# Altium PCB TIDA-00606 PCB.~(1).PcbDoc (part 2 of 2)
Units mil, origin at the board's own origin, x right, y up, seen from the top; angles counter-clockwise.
Board outline 3100 x 2950 mil, 4 copper layers (Top Layer, InternalPlane1, MidLayer1, Bottom Layer); 112 components, 59 nets, 260 pads, 440 vias.
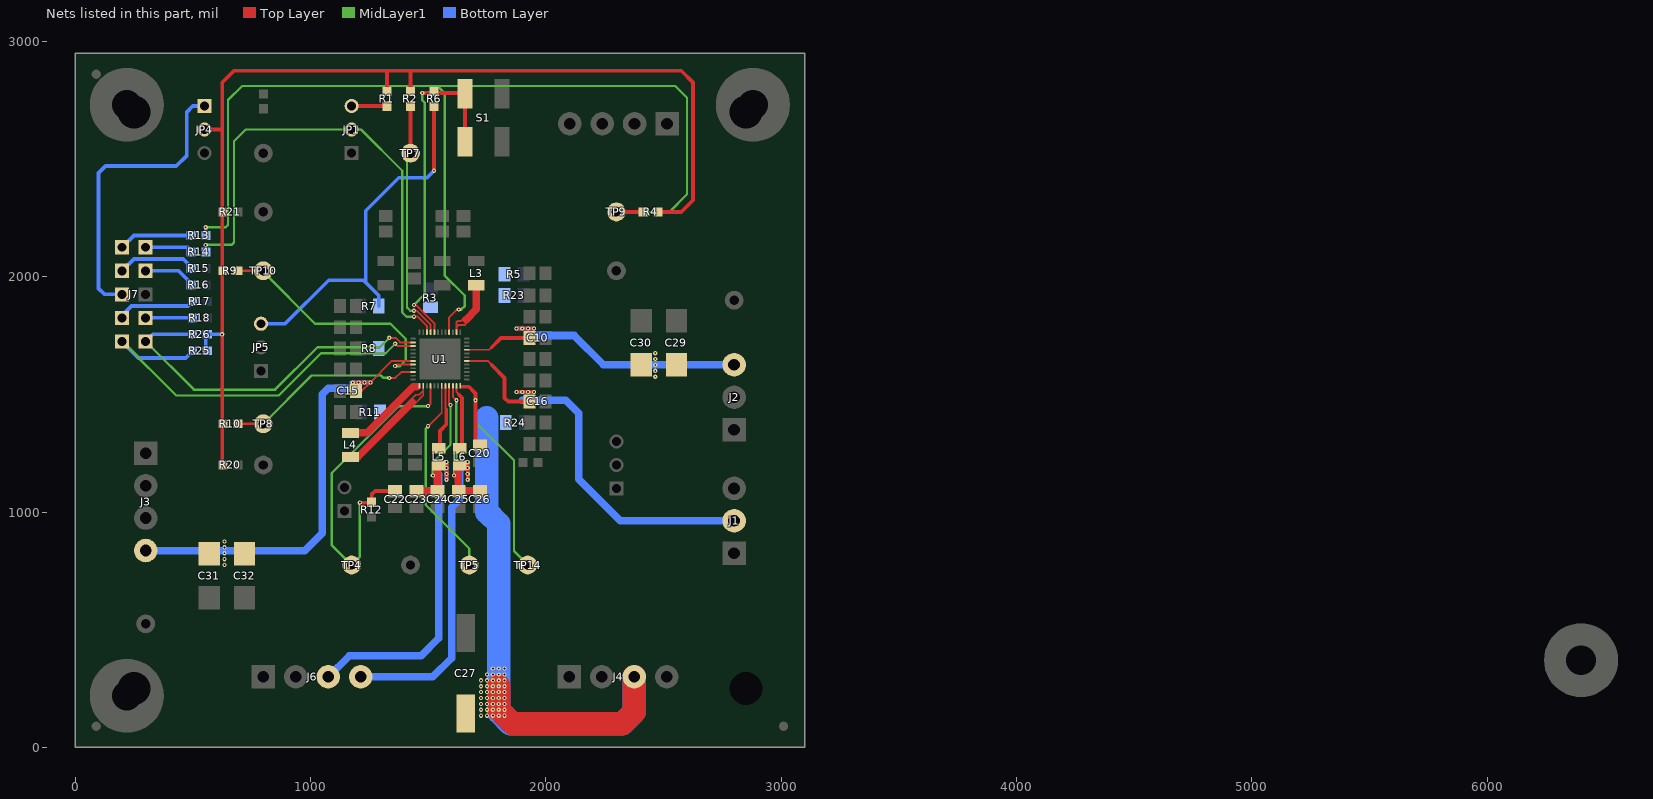
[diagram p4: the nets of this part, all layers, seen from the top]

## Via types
v1: diameter 18, hole 8, Top Layer to Bottom Layer, tented both sides, 440 vias

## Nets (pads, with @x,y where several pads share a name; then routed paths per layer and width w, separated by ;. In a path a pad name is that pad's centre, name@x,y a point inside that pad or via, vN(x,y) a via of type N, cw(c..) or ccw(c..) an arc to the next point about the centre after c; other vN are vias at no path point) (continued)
L3: L3.1 U1.38 | length 314.1
  Top Layer w8: U1.38@1620.87,1768.11 1620.87,1785.3 ; 1653.93,1827.07 1637.87,1811 1625,1811 1620.87,1806.87 1620.87,1785.3 ; 1677,1816 1656,1795 1630.57,1795 1620.87,1785.3
  Top Layer w32: 1661,1817 1705,1861 L3.1@1705,1963.82
L4A: L4.2 U1.13 | length 362.1
  Top Layer w32: L4.2@1170,1336.18 1241.18,1336.18 1437,1532 1451,1532
L4B: L4.1 U1.14 | length 526.6
  Top Layer w8: 1421,1472 1447.41,1498.41 1462.84,1498.41 1479.13,1514.7 ; 1440.07,1456.93 1479.13,1496 1479.13,1514.7 ; U1.14@1479.13,1531.89 1479.13,1514.7
  Top Layer w32: L4.1@1170,1233.82 1199.98,1233.82 1433.08,1466.92
LS1: C16.1 J1.2 U1.30 | length 1799.1
  Top Layer w8: U1.30@1668.11,1642.13 1752.87,1642.13 1770,1625
  Top Layer w16: 1770,1625 1825,1570 1825,1485 1840,1470 C16.1@1920,1470 ; v1(1875,1510) v1(1900,1510) v1(1925,1510) v1(1950,1510)
  Bottom Layer w16: v1(1875,1510) v1(1900,1510) v1(1925,1510) v1(1950,1510)
  Bottom Layer w32: 1900,1475 2085,1475 2140,1420 2140,1140 2317,963 J1.2@2800,963
LS2: C10.1 C29.1 C30.1 J2.3 U1.33 | length 1350.6
  Top Layer w8: U1.33@1668.11,1689.37 1759.37,1689.37 1770,1700
  Top Layer w16: 1770,1700 1810,1740 C10.1@1920,1740 ; v1(1875,1780) v1(1900,1780) v1(1925,1780) v1(1950,1780)
  Bottom Layer w16: v1(1875,1780) v1(1900,1780) v1(1925,1780) v1(1950,1780)
  Bottom Layer w32: 1925,1750 2120,1750 2245,1625 v1(2465,1625) 2800,1625 J2.3@2800,1625.59 J2.3@2800,1626
  other v1: 2465,1575 2465,1600 2465,1650 2465,1675
LS3: C15.2 C31.1 C32.1 J3.4 U1.7 | length 1930.6
  Top Layer w8: C15.2@1215,1515 1218.56,1515 1253.56,1550 1345.68,1642.13 U1.7@1431.89,1642.13
  Top Layer w16: v1(1180,1550) v1(1205,1550) v1(1230,1550) 1253.56,1550 v1(1255,1550)
  Bottom Layer w16: v1@1175,1550 v1(1180,1550) v1(1205,1550) v1(1230,1550) v1(1255,1550)
  Bottom Layer w32: J3.4@300,836 976,836 1050,910 1050,1500 1075,1525 1175,1525
  other v1: 635,775 635,800 635,825 635,850 635,875
NetC20_2: C20.2 TP14.1 U1.24 | length 1074.4
  Top Layer w16: 1641,1532 1673,1532 1701,1504 v1(1701,1475) C20.2@1701,1294
  MidLayer1 w10: v1(1701,1475) 1701,1384 1865,1220 1865,835 TP14.1@1925,775
NetJ7_1: J7.1 R13.1 | length 320.7
  Bottom Layer w16: J7.1@200,2125 250,2175 R13.1@493.5,2175 R13.1@500,2175
NetJ7_2: J7.2 R14.1 | length 208.3
  Bottom Layer w16: J7.2@300,2125 480,2125 R14.1@500,2105
NetJ7_3: J7.3 R15.1 | length 337.3
  Bottom Layer w16: J7.3@200,2025 250,2075 460,2075 R15.1@500,2035
NetJ7_4: J7.4 R16.1 | length 224.9
  Bottom Layer w16: J7.4@300,2025 440,2025 R16.1@500,1965
NetJ7_5: J7.5 JP4.1 | length 1276.8
  Bottom Layer w16: J7.5@200,1925 125,1925 100,1950 100,2440 130,2470 430,2470 475,2515 475,2700 500,2725 JP4.1@550,2725
NetJ7_7: J7.7 R17.1 | length 334.9
  Bottom Layer w16: J7.7@200,1825 200,1835 240,1875 480,1875 R17.1@500,1895
NetJ7_8: J7.8 R18.1 | length 200
  Bottom Layer w16: J7.8@300,1825 R18.1@498.5,1825 R18.1@500,1825
NetJP1_3: JP1.3 R1.1 | length 150
  Top Layer w16: JP1.3@1175,2725 R1.1@1325,2725
NetL5_2: L5.2 U1.20 | length 269.4
  Top Layer w8: U1.20@1573.62,1531.89 1573.62,1438.85 1576.87,1435.6
  Top Layer w16: L5.2@1538,1280 1550,1292 1550,1345 1577,1372 1577,1435.47 1576.87,1435.6
NetL6_2: L6.2 U1.23 | length 281.7
  Top Layer w8: U1.23@1620.87,1531.89 1620.87,1509.13 1630,1500
  Top Layer w16: L6.2@1625,1280 1627.59,1281.03 L6.2@1630,1282 ; L6.2@1628,1280 L6.2@1630,1282 ; 1630,1500 1644,1486 1644,1282 L6.2@1630,1282
NINT: R2.1 TP7.1 U1.45 | length 1021.1
  Top Layer w8: v1(1440,1855) 1451.86,1855 1510.63,1796.23 U1.45@1510.63,1768.11
  Top Layer w16: TP7.1@1425,2525 R2.1@1425,2723.5 R2.1@1425,2725
  MidLayer1 w10: TP7.1@1425,2525 1410,2510 1410,1869 1424,1855 v1(1440,1855)
NPFO: R10.2 TP8.1 U1.10 | length 851.3
  Top Layer w8: v1(1335,1570) 1361.21,1570 1386.09,1594.88 U1.10@1431.89,1594.88
  Top Layer w12: R10.2@680,1375 R10.2@691.5,1375 TP8.1@800,1375
  MidLayer1 w10: TP8.1@800,1375 1005,1580 1300,1580 1310,1570 v1(1335,1570)
NWAKEUP: R4.1 R13.2 TP9.1 U1.40 | length 4658
  Top Layer w8: U1.40@1589.37,1768.11 1589.37,1827.58 1621.79,1860 v1(1630,1860)
  Top Layer w16: TP9.1@2300,2275 R4.1@2413.5,2275 R4.1@2425,2275
  MidLayer1 w10: v1(555,2210) 640,2210 650,2220 650,2750 710,2810 1540,2810 ; v1@1630,1856 v1(1630,1860) 1640,1860 1656,1876 1656,1919 1570,2005 1570,2780 1540,2810 ; TP9.1@2300,2275 2525,2275 2600,2350 2600,2760 2550,2810 1540,2810
  Bottom Layer w16: R13.2@555,2175 v1(555,2210)
PB: R6.1 S1.2 S1.3 U1.44 | length 1462.2
  Top Layer w8: v1(1440,1880) 1448.07,1880 1526.38,1801.69 U1.44@1526.38,1768.11
  Top Layer w16: v1(1475,2780) 1653.5,2780 1656.1,2777.4 S1.3@1656.1,2572.6
  MidLayer1 w10: v1(1440,1880) 1485,1925 1485,2740 1475,2750 v1(1475,2780)
PFI: C22.2 R12.2 TP4.1 U1.16 | length 1490.3
  Top Layer w8: v1(1500,1450) 1510.63,1460.63 U1.16@1510.63,1531.89
  Top Layer w16: v1(1210,1040) 1260,1040 R12.2@1260,1041.5 1260,1075 1275,1090 C22.2@1340,1090
  MidLayer1 w10: v1(1210,1040) 1210,810 TP4.1@1175,775 1090,860 1090,1165 1375,1450 v1(1500,1450)
PGOOD: R9.2 TP10.1 U1.8 | length 1062.9
  Top Layer w8: v1(1360,1620) 1366.38,1626.38 U1.8@1431.89,1626.38
  Top Layer w10: R9.2@680,2025 R9.2@691.5,2025 TP10.1@800,2025
  MidLayer1 w10: TP10.1@800,2020 1020,1800 1340,1800 1405,1735 1405,1645 1380,1620 v1(1360,1620)
PGOOD_BU: TP5.1 U1.19 | length 861.6
  Top Layer w8: v1(1500,1365) 1557.87,1422.87 U1.19@1557.87,1531.89
  MidLayer1 w10: v1(1500,1365) 1490,1355 1490,1030 1675,845 TP5.1@1675,775
PWR_EN: JP1.2 R14.2 U1.46 | length 2145.6
  Top Layer w8: v1(1440,1830) 1455.64,1830 1494.88,1790.76 U1.46@1494.88,1768.11
  MidLayer1 w10: v1(555,2135) 665,2135 675,2145 675,2575 725,2625 JP1.2@1175,2625 1215,2625 1390,2450 1390,1848 1408,1830 v1(1440,1830)
  Bottom Layer w16: R14.2@555,2105 v1(555,2135)
SCL: J7.9 R25.1 U1.3 | length 1768.8
  Top Layer w8: v1(1360,1715) 1369.88,1705.12 U1.3@1431.89,1705.12
  MidLayer1 w10: J7.9@200,1720 J7.9@200,1725 430,1495 865,1495 1045,1675 1320,1675 v1(1360,1715)
  Bottom Layer w16: J7.9@200,1725 270,1655 470,1655 R25.1@500,1685
SDA: J7.10 R26.1 U1.2 | length 1528.3
  Top Layer w8: v1(1335,1740) 1361.87,1740 1381,1720.87 U1.2@1431.89,1720.87
  MidLayer1 w10: J7.10@300,1725 505,1520 850,1520 1030,1700 1295,1700 v1(1335,1740)
  Bottom Layer w16: J7.10@300,1725 330,1755 R26.1@498.5,1755 R26.1@500,1755
VDCDC5: C23.2 C24.2 J6.3 L5.1 U1.21 | length 1987.6
  Top Layer w8: U1.21@1589.37,1531.89 1589.37,1460.63 v1(1595,1455) v1@1595,1450
  Top Layer w16: v1(1578,1137) v1(1578,1162) v1(1578,1187) v1(1578,1212)
  Top Layer w32: C23.2@1448,1090 1538,1090 L5.1@1538,1190
  MidLayer1 w10: v1(1520,1155) 1520,1211 1595,1286 v1(1595,1455)
  Bottom Layer w16: v1(1578,1137) v1(1578,1162) v1(1578,1187) v1(1578,1212)
  Bottom Layer w32: J6.3@1076,300 1166,390 1470,390 1545,465 1545,1160
VDCDC6: C25.2 C26.2 J6.4 L6.1 U1.22 | length 1959.8
  Top Layer w8: U1.22@1605.12,1531.89 1605.12,1489.88 v1(1620,1475)
  Top Layer w16: v1(1668,1137) v1(1668,1162) v1(1668,1187) v1(1668,1212)
  Top Layer w32: L6.1@1628,1190 1628,1090 C26.2@1718,1090
  MidLayer1 w10: v1(1610,1155) 1610,1211 1620,1221 v1(1620,1475)
  Bottom Layer w16: v1(1668,1137) v1(1668,1162) v1(1668,1187) v1(1668,1212)
  Bottom Layer w32: J6.4@1210,300 J6.4@1213.39,300 1520,300 1600,380 1600,1020 1635,1055 1635,1175
VIO: JP4.2 R1.2 R2.2 R4.2 R9.1 R10.1 R20.1 R21.2 R25.2 R26.2 | length 4737.1
  Top Layer w16: JP4.2@550,2625 625,2625 ; R20.1@625,1200 v1(625,1755) 625,2275 625,2625 ; R1.2@1325,2780 R1.2@1325,2786.5 1325,2875 ; R2.2@1425,2780 R2.2@1425,2786.5 1425,2875 ; R4.2@2480,2275 2575,2275 2625,2325 2625,2825 2575,2875 1425,2875 ; 625,2625 625,2825 675,2875 1325,2875 ; 1325,2875 1425,2875
  Bottom Layer w16: R25.2@555,1685 555,1755 R26.2@561.5,1755 v1(625,1755)
VSYS: C27.1 J4.3 JP5.3 R3.2 R5.2 R6.2 R7.1 R8.1 R11.1 R23.2 R24.2 | length 4499.9
  Top Layer w16: v1(1525,2450) R6.2@1525,2723.5 R6.2@1525,2725
  Top Layer w100: v1(1800,260) v1(1800,235) v1(1800,210) v1(1800,185) v1(1800,160) v1(1825,135) 1860,100 2325,100 2376,151 J4.3@2376,300
  Bottom Layer w16: JP5.3@790,1800 892.47,1800 1077.47,1985 1225,1985 1235,1975 ; R7.1@1290,1875 1290,1920 1235,1975 ; v1(1525,2450) 1495,2420 1375,2420 1235,2280 1235,1975
  Bottom Layer w40: J4.3@2375,301 J4.3@2376,300
  Bottom Layer w100: 1750,1400 1750,1000 1800,950 v1(1800,335) v1(1800,310) v1(1800,285) v1(1800,260) v1(1800,235) v1(1800,210) v1(1800,185) v1(1800,160) 1800,150 1850,100 2325,100 2376,151 2376,300 J4.3@2376,301
  other v1: 1725,135 1750,135 1775,135 1800,135 1725,160 1750,160 1775,160 1825,160 1725,185 1750,185 1775,185 1825,185 1725,210 1750,210 1775,210 1825,210 1725,235 1750,235 1775,235 1825,235 1725,260 1750,260 1775,260 1825,260 1725,285 1750,285 1775,285 1825,285 1750,310 1775,310 1825,310 1775,335 1825,335
pads on no net: FID1.1 FID2.1 FID3.1 H1.1 H2.1 H3.1 H4.1 H5.0 H6.0 H7.0 H8.0 H9.0 H10.0 H11.0 H12.0 U1.28 U1.29

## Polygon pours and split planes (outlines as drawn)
GND on MidLayer1 "Mid Layer-GND" (solid, remove dead copper, pour order 8): 0,0 3100,0 3100,2950 0,2950
GND on Top Layer "Top Layer-GND" (solid, remove dead copper, pour order 5): 0,0 3100,0 3100,2950 0,2950
VSYS on Bottom Layer "Bottom Layer-VSYS" (solid, remove dead copper, pour order 3): 1837,1275 1260,1275 1260,2100 1837,2100
GND on Bottom Layer "Bottom Layer-GND" (solid, remove dead copper, pour order 7): 0,0 3100,0 3100,2950 0,2950
GND on InternalPlane1 (split plane): 3079.9,20.1 20.1,20.1 20.1,2929.9 3079.9,2929.9

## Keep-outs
Keep-Out Layer:
  lines w10: 3100,-5 0,-5 ; 3105,0 3105,2950 ; -5,0 ccw(c0,0) 0,-5 ; -5,0 ccw(c0,0) 0,-5 ; -5,0 ccw(c0,0) 0,-5 ; -5,0 ccw(c0,0) 0,-5 ; -5,0 ccw(c0,0) 0,-5 ; -5,0 ccw(c0,0) 0,-5 ; -5,0 -5,2950 ; -5,2950 cw(c0,2950) 0,2955 ; -5,2950 cw(c0,2950) 0,2955 ; -5,2950 cw(c0,2950) 0,2955 ; -5,2950 cw(c0,2950) 0,2955 ; -5,2950 cw(c0,2950) 0,2955 ; -5,2950 cw(c0,2950) 0,2955 ; 0,2955 3100,2955 ; 3100,2955 cw(c3100,2950) 3105,2950 ; 3100,2955 cw(c3100,2950) 3105,2950 ; 3100,2955 cw(c3100,2950) 3105,2950 ; 3100,2955 cw(c3100,2950) 3105,2950 ; 3100,2955 cw(c3100,2950) 3105,2950 ; 3100,2955 cw(c3100,2950) 3105,2950
  text ".Layer_Name" at 577,-858.49 h60

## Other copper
Top Layer:
  pour cut-out: 1505,1250 1660,1250 1660,1220 1505,1220
  pour cut-out: 1115,1310 1225,1310 1225,1255 1115,1255
  pour cut-out: 1650,2040 1760,2040 1760,1985 1650,1985
  pour cut-out: 1505,2040 1615,2040 1615,1985 1505,1985
  pour cut-out: 1265,2045 1375,2045 1375,1990 1265,1990
  region net IN_DC2: 1400,1915 1480,1915 1455,1890
  region net IN_DC2: 1400,2015 1479.37,2015 1480,1915 1400,1915
  region net IN_DC2: 1521,1823 1538,1806 1546,1806 1546,1835
  region net L3: 1625,1811 1620.87,1806.87 1620.87,1788 1623.57,1788 1630.57,1795 1656,1795 1677,1816 1661,1832 1661,1833 1659.87,1833 1637.87,1811
  region net L4B: 1421,1472 1438,1455 1479,1496 1479.13,1496 1479.13,1514.7 1462.84,1498.41 1447.41,1498.41
  region net L2: 1554,1868 1586,1868 1586,1861 1554,1829
  region net CC: 2036,1160 2036,1225 1945,1225 1945,1160
  region net 1V1_VCC_GXB: 1600,2218 1535,2218 1535,2127 1600,2127
  region net 2V5: 1690,2218 1625,2218 1625,2127 1690,2127
  region net IN_DC3: 1874.5,2055 1874.5,1990 1965.5,1990 1965.5,2055
  region net IN_DC4: 1177,1465 1177,1400 1268,1400 1268,1465
  region net IN_DC1: 1177,1915 1177,1850 1268,1850 1268,1915
  region net IN_LDO: 1177,1735 1177,1670 1268,1670 1268,1735
  region net LS3: 1177,1555 1177,1490 1268,1490 1268,1555
  region net IN_LS3: 1177,1645 1177,1580 1268,1580 1268,1645
  region net 1V8: 1177,1825 1177,1760 1268,1760 1268,1825
  region net LS1: 1867,1510 1867,1445 1958,1445 1958,1510
  region net IN_LS1: 1867,1600 1867,1535 1958,1535 1958,1600
  region net IN_LS2: 1867,1690 1867,1625 1958,1625 1958,1690
  region net LS2: 1867,1780 1867,1715 1958,1715 1958,1780
  region net IN_BIAS: 1874,1960 1874,1895 1965,1895 1965,1960
  region net LS3: 740,885 525,885 525,765 740,765
  region net LS2: 2360,1565 2575,1565 2575,1685 2360,1685
  region net VDCDC5: 1578,1220 1513,1220 1513,1129 1578,1129
  region net VDCDC6: 1668,1220 1603,1220 1603,1129 1668,1129
  region net INT_LDO: 1867,1870 1867,1805 1958,1805 1958,1870
  region net VSYS: 1620,50 1850,50 1850,350 1750,350 1620,220
  region net IN_BU: 1867,1420 1867,1355 1958,1355 1958,1420
  region net 1V1_VCC: 1365,2225 1275,2225 1275,2130 1365,2130
  region net L1: 1285,1945 1285,1890 1315,1860 1355,1860 1355,1945
  region net IN_DC1: 1395,1755 1380,1740 1385,1735 1415,1735 1415,1740
  region net IN_LDO: 1245,1730 1265,1730 1321,1674 1330,1670 1245,1670
  region net 1V8: 1260,1820 1285,1820 1310,1795 1310,1725 1300,1725 1260,1765
  region net IN_DC4: 1268,1465 1328,1525 1365,1525 1365,1497 1268,1400
  region net LS3: 1268,1490 1318.56,1540.56 1318.56,1613.56 1255,1550
  region net IN_LS3: 1268,1580 1335,1647 1335,1660 1240,1660 1230,1650 1230,1580
  region net IN_DC3: 1870,2052.5 1870,1987.5 1961,1987.5 1961,2052.5
  region net L2: 1600,1985 1600,1875 1560,1835 1555,1835 1554,1848.5 1525,1875 1525,1985
  region net L3: 1670,1985 1740,1985 1740,1875 1710,1845 1670,1845
  region net 3V3: 1494.88,1490.54 1391,1386.66 1391,1368 1333,1310 1333,1242 1473,1242 1473,1450 1494.88,1471.88
  region net NetL5_2: 1516.46,1250 1516.46,1326.46 1570,1380 1585,1375 1585,1250
  region net NetL6_2: 1665,1250 1605,1250 1605,1415 1640,1440 1650,1440 1665,1415
  text ".Layer_Name" at 577,-858.49 h60
Bottom Layer:
  region net 2V5: 1625,2218 1690,2218 1690,2127 1660,2127 1625,2162
  region net GND: 1460,1740 1640,1740 1640,1560 1460,1560
  region net IN_BIAS: 1965,1892.5 1965,1965 1875,1965 1874,1892.5
  region net CC: 1945,1225 1945,1160 2036,1160 2036,1225
  region net IN_DC4: 1165,1465 1165,1400 1250,1400 1250,1465
  region net IN_LDO: 1165,1735 1165,1665 1250,1665 1251,1737.5
  region net IN_DC1: 1159.5,1915 1159.5,1850 1250.5,1850 1250.5,1915
  region net IN_DC3: 1965.5,1990 1965.5,2055 1874.5,2055 1874.5,1990
  region net IN_DC2: 1400,1915 1550,1915 1550,1985 1400,1985
  region net 1V8: 1260.5,1760 1260.5,1825 1169.5,1825 1169.5,1760
  region net LS3: 1260.5,1490 1260.5,1555 1169.5,1555 1169.5,1490
  region net IN_LS3: 1265.5,1580 1265.5,1645 1174.5,1645 1174.5,1580
  region net LS1: 1958,1445 1958,1510 1867,1510 1867,1445
  region net IN_LS1: 1958,1535 1958,1600 1867,1600 1867,1535
  region net IN_LS2: 1958,1625 1958,1690 1867,1690 1867,1625
  region net LS2: 1958,1715 1958,1780 1867,1780 1867,1715
  region net LS3: 740,885 525,885 525,765 740,765
  region net LS2: 2360,1565 2575,1565 2575,1685 2360,1685
  region net VDCDC5: 1513,1129 1578,1129 1578,1220 1548,1220 1513,1185
  region net VDCDC6: 1602,1129 1667,1129 1667,1220 1637,1220 1602,1185
  region net 1V1_VCC: 1285,2225 1355,2225 1355,2127 1325,2127 1285,2160
  region net 1V1_VCC_GXB: 1535,2218 1600,2218 1600,2127 1570,2127 1535,2162
  region net 2V5: 1625,2218 1690,2218 1690,2127 1660,2127 1625,2162
  region net INT_LDO: 1958,1805 1958,1870 1867,1870 1867,1805
  region net VSYS: 1620,50 1850,50 1850,390 1750,390 1620,260
  region net IN_BU: 1958,1355 1958,1420 1867,1420 1867,1355
  region net IN_DC3: 1961,1987.5 1961,2052.5 1870,2052.5 1870,1987.5
  text ".Layer_Name" at 577,-858.49 h60

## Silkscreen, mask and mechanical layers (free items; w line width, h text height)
Top Overlay:
  region: 3050,2305 2750,2305 2750,2205 3050,2205
  lines w10: 1025,900 1025,2370 2110,2370 2110,900 1025,900
  text "DC1" at 2130,2880 h40 r180
  text "DC2" at 2290,2880 h40 r180
  text "DC3" at 2430,2880 h40 r180
  text "GND" at 2570,2880 h40 r180
  text "V3p3" at 370,2710 h30
  text "VIO" at 1005,2710 h30
  text "DC4" at 400,2510 h30
  text "GND" at 1005,2510 h30
  text "TIDA-00478" at 2445,2105 h50
  text "A" at 3010,2105 h50
  text "-" at 2945,2100 h50
  text "TPS65218" at 2665,2025 h50
  text "VSYS" at 610,1780 h30
  text "AC_D" at 610,1680 h30
  text "LS2" at 3030,1670 h40 r90
  text "GND" at 615,1580 h30
  text "+" at 2320,1560 h40 r90
  text "GND" at 70,1390 h40 r270
  text "IN_LS2" at 3030,1390 h40 r90
  text "DC3" at 2370,1290 h30
  text "LD01" at 70,1230 h40 r270
  text "GND" at 3030,1230 h40 r90
  text "EXT" at 2370,1080 h30
  text "EXT" at 3030,1070 h40 r90
  text "IN_LS3" at 70,1050 h40 r270
  text "GND" at 1070,960 h30 r90
  text "LS1" at 3030,910 h40 r90
  text "+" at 845,865 h40 r90
  text "LS3" at 70,790 h40 r270
  text "GND" at 3030,750 h40 r90
  text "GND" at 710,70 h40
  text "DC4" at 870,70 h40
  text "DC5" at 1030,70 h40
  text "DC6" at 1190,70 h40
  text "GND" at 2030,70 h40
  text "GND" at 2170,70 h40
  text "VSYS" at 2310,70 h40
  text "CC" at 2510,70 h40
  text ".Layer_Name" at 577,-858.49 h60
Bottom Overlay:
  text ".Layer_Name" at 577,-858.49 h60
Top Paste:
  text ".Layer_Name" at 577,-858.49 h60
Bottom Paste:
  text ".Layer_Name" at 577,-858.49 h60
Top Solder:
  text ".Layer_Name" at 577,-858.49 h60
  text ".Layer_Name" at 577,-858.49 h60
Bottom Solder:
  text ".Layer_Name" at 577,-858.49 h60
Drill Guide:
  text ".Layer_Name" at 577,-858.49 h60
M1 Board Outline:
  the board outline again, w10
  text ".Layer_Name" at 577,-858.49 h60
M2 Board Dimensions:
  rectangle: 0,-285.5 125,-160.5
  rectangle: 125,-410.5 500,-285.5
  lines w7: 0,-285.5 1000,-285.5 ; 125,-410.5 125,-160.5 ; 250,-410.5 250,-160.5 ; 500,-410.5 500,-160.5 ; 750,-410.5 750,-160.5 ; 0,-410.5 1000,-410.5 1000,-160.5 0,-160.5 0,-410.5
  text ".Layer_Name" at 577,-858.49 h60
M3 3D STEP Top:
  text ".Layer_Name" at 577,-858.49 h60
M4 3D STEP Bottom:
  text ".Layer_Name" at 577,-858.49 h60
M5 Assembly Top:
  lines w10: -292,-930.17 6308,-930.17 ; -292,-726.83 6310,-726.83 ; -292,-523.5 -292,-1133.5 3713,-1133.5 6310,-1133.5 6310,-523.5 -291.5,-523.5 -291.5,-1133.5 1284,-1133.5 ; 2173,-1133.5 2173,-523.5 ; 3440,-726.83 3440,-523.5 ; 4280,-726.83 4280,-523.5 ; 4902,-1140 4902,-937.17
  text "COMPONENTS MARKED 'DNP' SHOULD NOT BE POPULATED." at 1153.5,-318.5 h60
  text "ASSEMBLY VARIANT:" at 1153,-434 h60
  text ".VariantName" at 2189,-434 h60
  text "PCB VIEWED FROM TOP SIDE" at -228.5,-655.67 h60
  text "BOARD #:" at 2248,-655.67 h60
  text ".PRJ_Number" at 2793.5,-655.67 h60
  text "REV:" at 3638,-655.67 h60
  text ".PCB_Rev" at 3929.5,-655.67 h60
  text "SVN REV:" at 4476,-655.67 h60
  text ".VersionControl_RevNumber" at 4982,-655.67 h60
  text "IGNORE ->" at -228.5,-858.49 h60
  text "PLOT NAME =" at -228.5,-1064.34 h60
  text ".plot_File_Name" at 577,-1064.34 h60
  text "GENERATED    :" at 2250,-1064.34 h60
  text ".Print_Date" at 3119.5,-1064.34 h60
  text ".Print_Time" at 3848.5,-1064.34 h60
  text "TEXAS INSTRUMENTS" at 5113,-1064.34 h60
M6 Assembly Bottom:
  lines w10: -292.5,-727.33 6309.5,-727.33 ; -290.5,-930.67 6309.5,-930.67 ; 1115.5,-1140.5 1115.5,-937.67 ; 1737.5,-727.33 1737.5,-524 ; 2577.5,-727.33 2577.5,-524 ; 3844.5,-1134 3844.5,-524 ; 4733.5,-1134 6309,-1134 6309,-524 -292.5,-524 -292.5,-1134 2304.5,-1134 6309.5,-1134 6309.5,-524
  text "COMPONENTS MARKED 'DNP' SHOULD NOT BE POPULATED." at 6102,-318 h60
  text ".VariantName" at 5058,-434 h60
  text "ASSEMBLY VARIANT:" at 6097,-434 h60
  text ".VersionControl_RevNumber" at 1035.5,-656.17 h60
  text "SVN REV:" at 1541.5,-656.17 h60
  text ".PCB_Rev" at 2088,-656.17 h60
  text "REV:" at 2379.5,-656.17 h60
  text ".PRJ_Number" at 3224,-656.17 h60
  text "BOARD #:" at 3769.5,-656.17 h60
  text "PCB VIEWED FROM BOTTOM SIDE" at 6246,-656.17 h60
  text "IGNORE ->" at 2547.85,-858.49 h60
  text "TEXAS INSTRUMENTS" at 904.5,-1064.84 h60
  text ".Print_Time" at 2169,-1064.84 h60
  text ".Print_Date" at 2898,-1064.84 h60
  text "GENERATED    :" at 3767.5,-1064.84 h60
  text ".plot_File_Name" at 5440.5,-1064.84 h60
  text "PLOT NAME =" at 6246,-1064.84 h60
M9 Title Sheet:
  drawing of 57 lines, arcs and shapes, not listed
  text "1" at 739.84,8036.5 h70
  text "2" at 3235.5,8036.5 h70
  text "3" at 5724.84,8036.5 h70
  text "4" at 8231.51,8036.5 h70
  text "5" at 10730.5,8036.5 h70
  text "6" at 13235.5,8036.5 h70
  text "A" at -416.5,6893.5 h70
  text "A" at 14383.5,6893.5 h70
  text "B" at -416.5,4513.5 h70
  text "B" at 14383.5,4513.5 h70
  text "C" at -416.5,2138.5 h70
  text "C" at 14383.5,2138.5 h70
  text "PROJECT TITLE:" at 11343.5,277.5 h45
  text ".PRJ_Title" at 11393.5,144.17 h70
  text "DESIGNED FOR:" at 11343.5,-23.5 h45
  text ".PRJ_Customer" at 11393.5,-163.5 h70
  text "D" at -416.5,-231.5 h70
  text "D" at 14383.5,-231.5 h70
  text "FILE NAME:" at 11343.5,-323.5 h45
  text ".PCB_File_Name_No_Path" at 11393.5,-443.5 h70
  text "Texas Instruments (TI) and/or its licensors do not warrant the accuracy or completeness of this specification" at 6374,-605.34 h45
  text "ENGINEER:" at 11343.5,-613.5 h45
  text "LAYOUT BY:" at 12848.5,-613.5 h45
  text "or any information contained therein. TI and/or its licensors do not warrant that this design will meet" at 6329.01,-718 h45
  text ".PRJ_Engineer" at 11393.5,-768.49 h70
  text ".PCB_Layout" at 12899,-768.49 h70
  text "the specifications, will be suitable for your application or fit for any particular purpose, or will operate in" at 6329.01,-830.67 h45
  text ".Layer_Name" at 577,-858.49 h60
  text "ALTIUM DESIGNER VERSION:" at 12848.5,-923.5 h45
  text "an implementation. TI and/or its licensors do not warrant that the design is production worthy. You should" at 6329.01,-943.33 h45
  text "completely validate and test your design implementation to confirm the system functionality for your application." at 6374,-1056 h45
  text ".print_Scale" at 11393.5,-1056.83 h70
  text ".Application_BuildNumber" at 12899,-1056.83 h70
  text "1" at 739.84,-1263.5 h70
  text "2" at 3235.5,-1263.5 h70
  text "3" at 5724.84,-1263.5 h70
  text "4" at 8231.51,-1263.5 h70
  text "5" at 10730.5,-1263.5 h70
  text "6" at 13235.5,-1263.5 h70
M10 Fab Notes:
  drawing of 185 lines, arcs and shapes, not listed
  text "DESIGN INFORMATION" at 12381.02,5910 h60
  text "MIN. TRACK WIDTH:" at 11736.46,5730 h60
  text "8" at 12832.7,5730 h60
  text "MIL" at 12987.46,5730 h60
  text "MIN. CLEARANCE:" at 11736.46,5598 h60
  text "0.2" at 12772.7,5598 h60
  text "mm" at 12987.46,5598 h60
  text "MIN. VIA PAD SIZE:" at 11736.46,5466 h60
  text "24" at 12802.71,5466 h60
  text "MIL" at 12987.46,5466 h60
  text "0.05mm (2MIL)" at 12431.46,5324.29 h60
  text "MINIMUM ANNULAR RING" at 11407.23,5320 h60
  text "EXTERNAL" at 13139.46,5320 h60
  text "PER" at 11607.23,5202 h60
  text "IPC-D-275 CLASS 2 LEVEL C" at 11827.23,5202 h60
  text "MIL, HOLES" at 13315.46,5089.71 h60
  text "+/-" at 12923,5089 h60
  text "+/-" at 13777,5089 h60
  text "REGISTRATION TOLERANCES:" at 11407.23,5084 h60
  text "METAL" at 12607,5084 h60
  text "5" at 13183.2,5084 h60
  text "3" at 14016.2,5084 h60
  text "MIL" at 14132.46,5084 h60
  text "MATERIAL:" at 11332.46,4874.54 h60
  text "FR-4 High Tg" at 12318.9,4734.21 h60
  text "FR-408" at 11753.46,4725.64 h60
  text "X" at 12165.46,4725.64 h60
  text "OTHER" at 13241.46,4725.64 h60
  text "62 MIL (1.6mm) +/-10%" at 12073.56,4562.92 h60
  text "THICKNESS:" at 11407.23,4558.64 h60
  text "X" at 11945.4,4558.64 h60
  text "OTHER" at 13358.46,4558.64 h60
  text "TOLERANCE:" at 11407.23,4400.64 h60
  text "X" at 12246.53,4400.64 h60
  text "ANSI IPC-6012 TYPE 3 CLASS 2" at 12433.48,4400.64 h60
  text "OTHER +/-" at 12433.46,4244.64 h60
  text "BOW & TWIST:" at 11407.23,4087.64 h60
  text "X" at 12246.53,4087.64 h60
  text "ANSI IPC-6012 TYPE 3 CLASS 2" at 12433.48,4087.64 h60
  text "OTHER +/-" at 12433.46,3929.13 h60
  text "DRILLING:" at 11332.46,3790.64 h60
  text "REFERENCE:" at 11407.23,3673.64 h60
  text "X" at 12055.46,3673.64 h60
  text "AS SHOWN" at 12242.46,3673.64 h60
  text "X" at 12956.46,3673.64 h60
  text "NC_DRILL FILES" at 13093.46,3673.64 h60
  text "PTH MIN COPPER THICKNESS:" at 11407.23,3515.64 h60
  text "X" at 12757.46,3515.64 h60
  text "1MIL" at 12894.46,3515.64 h60
  text "OTHER" at 13391.46,3515.64 h60
  text "BOARD FINISH:" at 11332.46,3356.64 h60
  text "SILKSCREEN:" at 11487.68,3238.64 h60
  text "X" at 12436.46,3238.64 h60
  text "TOP" at 12562.46,3238.64 h60
  text "X" at 12946.46,3238.64 h60
  text "BOTTOM" at 13073.46,3238.64 h60
  text "SILKSCREEN COLOR:" at 11487.68,3071.64 h60
  text "X" at 12435.42,3071.64 h60
  text "WHITE" at 12562.46,3071.64 h60
  text "OTHER" at 13073.46,3071.64 h60
  text "SOLDER RESIST COLOR:" at 11487.68,2901.64 h60
  text "X" at 12645,2745 h60
  text "GREEN" at 12182.46,2742.44 h60
  text "BLUE" at 12773.46,2742.44 h60
  text "OTHER" at 13311.46,2742.44 h60
  text "IMMERSION GOLD (ENIG)" at 12393.46,2553.92 h60
  text "ENEPIG" at 13731,2550.64 h60
  text "SURFACE FINISH:" at 11332.46,2549.64 h60
  text "X" at 12206.51,2549.64 h60
  text "IMM. TIN/SILVER OR EQUIV" at 11662,2392.64 h60
  text "OTHER" at 13093.46,2392.64 h60
  text "ARRAY/PANEL:" at 11332.46,2213.64 h60
  text "CUT AND TRIM PER MECH LAYER 1" at 12393.46,2209.35 h60
  text "N.C. ROUTE" at 12393.46,2057.64 h60
  text "X" at 13072.46,2057.64 h60
  text "V. SCORE" at 13259.46,2057.64 h60
  text "CERTIFICATION:" at 11332.46,1920.64 h60
  text "MATERIALS AND WORKMANSHIP FOR ALL PCBS" at 12057.46,1920.64 h60
  text "TO MEET OR EXCEED THE REQUIREMENTS OF:" at 12057.46,1822.64 h60
  text "X" at 11683.96,1686.13 h60
  text "ANSI IPC-A-600F CLASS ->" at 11822.96,1686.13 h60
  text "X" at 13462.02,1686.13 h60
  text "2" at 13580.96,1686.14 h60
  text "1" at 13265.96,1684.64 h60
  text "3" at 13934.96,1684.64 h60
  text "X" at 11686.02,1526.64 h60
  text "UL 94V-0" at 11822.96,1526.64 h60
  text "X" at 12498.02,1526.64 h60
  text "RoHS" at 12634.96,1526.64 h60
  text "OTHER" at 13279.36,1526.64 h60
  text "PER ORDER" at 13676.42,1526.64 h60
  text "ADDITIONAL REQUIREMENTS:" at 11332.46,1385.64 h60
  text "MICROSECTION:" at 11407.23,1270.64 h60
  text "YES" at 12312.96,1270.64 h60
  text "REQUIRED" at 13174.46,1114.49 h60
  text "BARE BOARD ELEC. TEST:" at 11407.23,1111.64 h60
  text "NONE" at 12712.96,1111.64 h60
  text "X" at 13047.46,1111.64 h60
  text "PER ORDER" at 13766.46,1111.64 h60
  text "MANUFACTURER'S UL:" at 11407.23,954.64 h60
  text "RAIL" at 12572.96,950.35 h60
  text "METAL" at 13064.77,950.35 h60
  text "X" at 13440,950 h60
  text "SILK" at 13576.46,950.35 h60
  text ".Layer_Name" at 577,-858.49 h60
M11 Gerber Information:
  lines w10: -292,-930.17 6308,-930.17 ; -292,-726.83 6310,-726.83 ; -292,-523.5 -292,-1133.5 3713,-1133.5 6310,-1133.5 6310,-523.5 -291.5,-523.5 -291.5,-1133.5 1284,-1133.5 ; 2173,-1133.5 2173,-523.5 ; 3440,-726.83 3440,-523.5 ; 4280,-726.83 4280,-523.5 ; 4902,-1140 4902,-937.17
  text "ALL ARTWORK VIEWED FROM TOP SIDE" at -228.5,-655.67 h60
  text "BOARD #:" at 2248,-655.67 h60
  text ".PRJ_Number" at 2793.5,-655.67 h60
  text "REV:" at 3638,-655.67 h60
  text ".PCB_Rev" at 3929.5,-655.67 h60
  text "SVN REV:" at 4476,-655.67 h60
  text ".VersionControl_RevNumber" at 4982,-655.67 h60
  text "LAYER NAME =" at -228.5,-858.49 h60
  text "PLOT NAME =" at -228.5,-1064.34 h60
  text ".plot_File_Name" at 577,-1064.34 h60
  text "GENERATED    :" at 2250,-1064.34 h60
  text ".Print_Date" at 3119.5,-1064.34 h60
  text ".Print_Time" at 3848.5,-1064.34 h60
  text "TEXAS INSTRUMENTS" at 5113,-1064.34 h60
M12 Stackup:
  lines w7: 11370,7009.75 14175,7009.75 ; 11370,7139.75 14175,7139.75 ; 11310,6182 ccw(c11352,6182) 11352,6140 14193,6140 ccw(c14193,6182) 14235,6182 14235,7253 ccw(c14193,7253) 14193,7295 11352,7295 ccw(c11352,7253) 11310,7253 11310,6182
  text "Layer Stack Up Detail for: HVL100A.PcbDoc" at 11370,7173.67 h59
  text "Layer" at 11370,7091.25 h30
  text "Gerber" at 12360.77,7091.25 h30
  text "Copper" at 12945.67,7091.25 h30
  text "Dielectric" at 13579.55,7091.25 h30
  text "Name" at 11370,7031.25 h30
  text "Document" at 12360.77,7031.25 h30
  text "Thickness" at 12945.67,7031.25 h30
  text "Material" at 13579.55,7031.25 h30
  text "Top Solder Mask" at 11370,6946.09 h42
  text "(.GTS)" at 12360.77,6946.09 h42
  text "Solder Resist" at 13579.55,6946.09 h42
  text "Top Layer" at 11370,6825.78 h42
  text "(.GTL)" at 12360.77,6825.78 h42
  text "2.8mil" at 12945.67,6825.78 h42
  text "FR-4" at 13579.55,6765.63 h42
  text "InternalPlane1" at 11370,6705.47 h42
  text "(.GP1)" at 12360.77,6705.47 h42
  text "2.1mil" at 12945.67,6705.47 h42
  text "FR-4" at 13579.55,6645.31 h42
  text "MidLayer1" at 11370,6585.16 h42
  text "(.G1)" at 12360.77,6585.16 h42
  text "2.1mil" at 12945.67,6585.16 h42
  text "FR-4" at 13579.55,6525 h42
  text "Bottom Layer" at 11370,6464.84 h42
  text "(.GBL)" at 12360.77,6464.84 h42
  text "2.8mil" at 12945.67,6464.84 h42
  text "Bottom Solder Mask" at 11370,6344.53 h42
  text "(.GBS)" at 12360.77,6344.53 h42
  text "Solder Resist" at 13579.55,6344.53 h42
  text ".Layer_Name" at 577,-858.49 h60
M13 Component Bodies Top:
  text ".Layer_Name" at 577,-858.49 h60
M14 Component Bodies Bottom:
  text ".Layer_Name" at 577,-858.49 h60
M15 Courtyards Top:
  the board outline again, w10
  text ".Layer_Name" at 577,-858.49 h60
M16 Courtyards Bottom:
  text ".Layer_Name" at 577,-858.49 h60
Drill Drawing:
  text ".legend" at 3307.5,870.5 h60
  text "Drill Table" at 3332.5,685.5 h60
  text ".Layer_Name" at 577,-858.49 h60

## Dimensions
0,0 to 3100,0 on M2 Board Dimensions
0,2950 to 0,0 on M2 Board Dimensions
0,-410.5 to 1000,-410.5 on M2 Board Dimensions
